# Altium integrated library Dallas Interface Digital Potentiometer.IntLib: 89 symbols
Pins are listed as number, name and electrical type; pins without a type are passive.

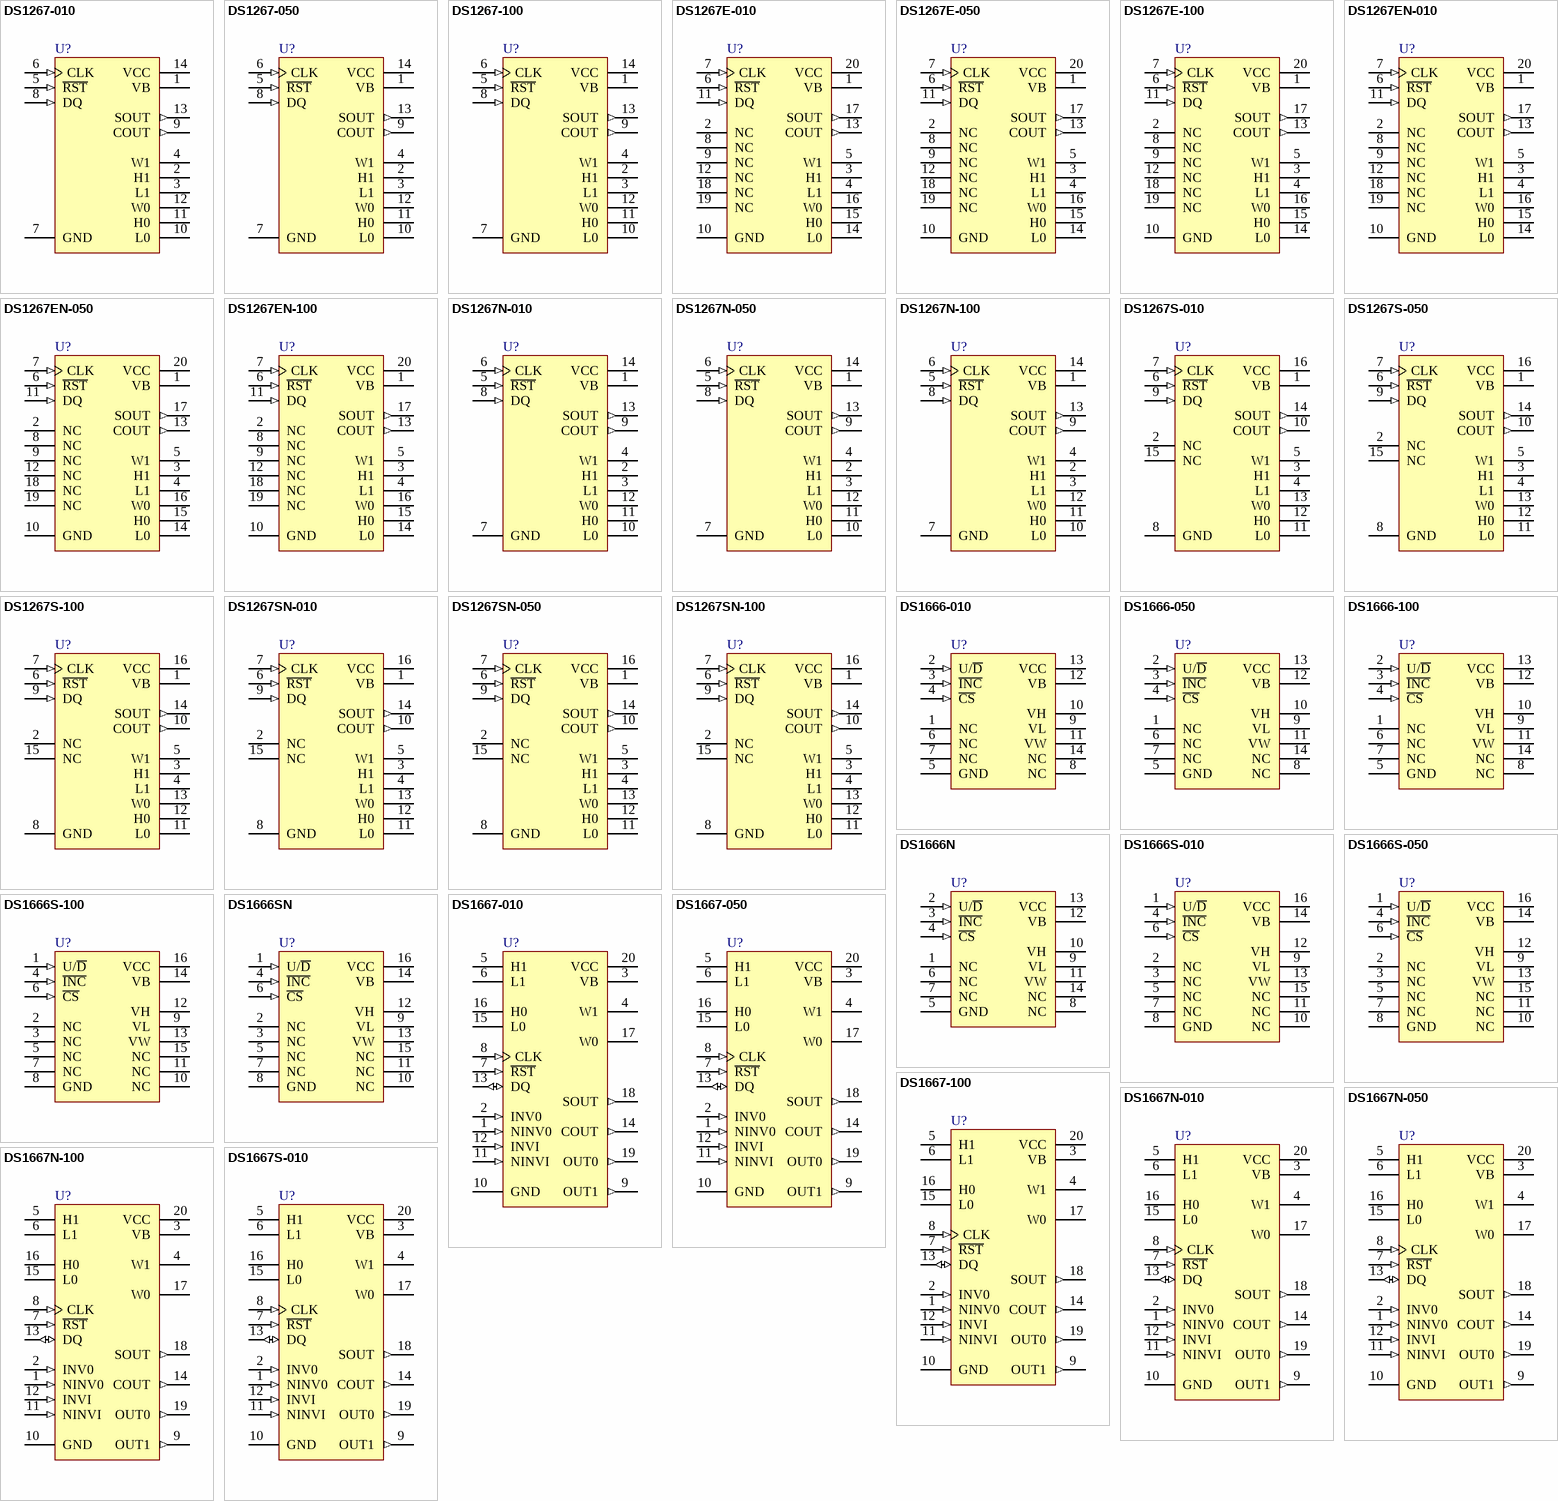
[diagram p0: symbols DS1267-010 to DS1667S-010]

## DS1267-010
designator U?
Dual Digital Potentiometer Chip
footprint DIP14 (DIP, 14-Leads, Row Spacing 7.62mm, Pitch 2.54mm, Body 19.31x6.35mm)
pins: 1 VB (power), 2 H1, 3 L1, 4 W1, 5 ~{RST} (in), 6 CLK (in), 7 GND (power), 8 DQ (in), 9 COUT (out), 10 L0, 11 H0, 12 W0, 13 SOUT (out), 14 VCC (power)

## DS1267-050
designator U?
Dual Digital Potentiometer Chip
footprint DIP14 (DIP, 14-Leads, Row Spacing 7.62mm, Pitch 2.54mm, Body 19.31x6.35mm)
pins: 1 VB (power), 2 H1, 3 L1, 4 W1, 5 ~{RST} (in), 6 CLK (in), 7 GND (power), 8 DQ (in), 9 COUT (out), 10 L0, 11 H0, 12 W0, 13 SOUT (out), 14 VCC (power)

## DS1267-100
designator U?
Dual Digital Potentiometer Chip
footprint DIP14 (DIP, 14-Leads, Row Spacing 7.62mm, Pitch 2.54mm, Body 19.31x6.35mm)
pins: 1 VB (power), 2 H1, 3 L1, 4 W1, 5 ~{RST} (in), 6 CLK (in), 7 GND (power), 8 DQ (in), 9 COUT (out), 10 L0, 11 H0, 12 W0, 13 SOUT (out), 14 VCC (power)

## DS1267E-010
designator U?
Dual Digital Potentiometer Chip; Note: Pin numbers 2, 8, 9, 12, 18 and 19 are Not Connected (NC)
footprint TSSOP20_N (TSOP, 20-Leads, Body 6.5x4.4mm, Pitch 0.65mm, IPC Medium Density)
footprint TSSOP20_L (TSOP, 20-Leads, Body 6.5x4.4mm, Pitch 0.65mm, IPC High Density)
footprint TSSOP20_M (TSOP, 20-Leads, Body 6.5x4.4mm, Pitch 0.65mm, IPC Low Density)
pins: 1 VB (power), 2 NC, 3 H1, 4 L1, 5 W1, 6 ~{RST} (in), 7 CLK (in), 8 NC, 9 NC, 10 GND (power), 11 DQ (in), 12 NC, 13 COUT (out), 14 L0, 15 H0, 16 W0, 17 SOUT (out), 18 NC, 19 NC, 20 VCC (power)

## DS1267E-050
designator U?
Dual Digital Potentiometer Chip; Note: Pin numbers 2, 8, 9, 12, 18 and 19 are Not Connected (NC)
footprint TSSOP20_N (TSOP, 20-Leads, Body 6.5x4.4mm, Pitch 0.65mm, IPC Medium Density)
footprint TSSOP20_L (TSOP, 20-Leads, Body 6.5x4.4mm, Pitch 0.65mm, IPC High Density)
footprint TSSOP20_M (TSOP, 20-Leads, Body 6.5x4.4mm, Pitch 0.65mm, IPC Low Density)
pins: 1 VB (power), 2 NC, 3 H1, 4 L1, 5 W1, 6 ~{RST} (in), 7 CLK (in), 8 NC, 9 NC, 10 GND (power), 11 DQ (in), 12 NC, 13 COUT (out), 14 L0, 15 H0, 16 W0, 17 SOUT (out), 18 NC, 19 NC, 20 VCC (power)

## DS1267E-100
designator U?
Dual Digital Potentiometer Chip; Note: Pin numbers 2, 8, 9, 12, 18 and 19 are Not Connected (NC)
footprint TSSOP20_N (TSOP, 20-Leads, Body 6.5x4.4mm, Pitch 0.65mm, IPC Medium Density)
footprint TSSOP20_L (TSOP, 20-Leads, Body 6.5x4.4mm, Pitch 0.65mm, IPC High Density)
footprint TSSOP20_M (TSOP, 20-Leads, Body 6.5x4.4mm, Pitch 0.65mm, IPC Low Density)
pins: 1 VB (power), 2 NC, 3 H1, 4 L1, 5 W1, 6 ~{RST} (in), 7 CLK (in), 8 NC, 9 NC, 10 GND (power), 11 DQ (in), 12 NC, 13 COUT (out), 14 L0, 15 H0, 16 W0, 17 SOUT (out), 18 NC, 19 NC, 20 VCC (power)

## DS1267EN-010
designator U?
Dual Digital Potentiometer Chip; Note: Pin numbers 2, 8, 9, 12, 18 and 19 are Not Connected (NC)
footprint TSSOP20_N (TSOP, 20-Leads, Body 6.5x4.4mm, Pitch 0.65mm, IPC Medium Density)
footprint TSSOP20_L (TSOP, 20-Leads, Body 6.5x4.4mm, Pitch 0.65mm, IPC High Density)
footprint TSSOP20_M (TSOP, 20-Leads, Body 6.5x4.4mm, Pitch 0.65mm, IPC Low Density)
pins: 1 VB (power), 2 NC, 3 H1, 4 L1, 5 W1, 6 ~{RST} (in), 7 CLK (in), 8 NC, 9 NC, 10 GND (power), 11 DQ (in), 12 NC, 13 COUT (out), 14 L0, 15 H0, 16 W0, 17 SOUT (out), 18 NC, 19 NC, 20 VCC (power)

## DS1267EN-050
designator U?
Dual Digital Potentiometer Chip; Note: Pin numbers 2, 8, 9, 12, 18 and 19 are Not Connected (NC)
footprint TSSOP20_N (TSOP, 20-Leads, Body 6.5x4.4mm, Pitch 0.65mm, IPC Medium Density)
footprint TSSOP20_L (TSOP, 20-Leads, Body 6.5x4.4mm, Pitch 0.65mm, IPC High Density)
footprint TSSOP20_M (TSOP, 20-Leads, Body 6.5x4.4mm, Pitch 0.65mm, IPC Low Density)
pins: 1 VB (power), 2 NC, 3 H1, 4 L1, 5 W1, 6 ~{RST} (in), 7 CLK (in), 8 NC, 9 NC, 10 GND (power), 11 DQ (in), 12 NC, 13 COUT (out), 14 L0, 15 H0, 16 W0, 17 SOUT (out), 18 NC, 19 NC, 20 VCC (power)

## DS1267EN-100
designator U?
Dual Digital Potentiometer Chip; Note: Pin numbers 2, 8, 9, 12, 18 and 19 are Not Connected (NC)
footprint TSSOP20_N (TSOP, 20-Leads, Body 6.5x4.4mm, Pitch 0.65mm, IPC Medium Density)
footprint TSSOP20_L (TSOP, 20-Leads, Body 6.5x4.4mm, Pitch 0.65mm, IPC High Density)
footprint TSSOP20_M (TSOP, 20-Leads, Body 6.5x4.4mm, Pitch 0.65mm, IPC Low Density)
pins: 1 VB (power), 2 NC, 3 H1, 4 L1, 5 W1, 6 ~{RST} (in), 7 CLK (in), 8 NC, 9 NC, 10 GND (power), 11 DQ (in), 12 NC, 13 COUT (out), 14 L0, 15 H0, 16 W0, 17 SOUT (out), 18 NC, 19 NC, 20 VCC (power)

## DS1267N-010
designator U?
Dual Digital Potentiometer Chip
footprint DIP14 (DIP, 14-Leads, Row Spacing 7.62mm, Pitch 2.54mm, Body 19.31x6.35mm)
pins: 1 VB (power), 2 H1, 3 L1, 4 W1, 5 ~{RST} (in), 6 CLK (in), 7 GND (power), 8 DQ (in), 9 COUT (out), 10 L0, 11 H0, 12 W0, 13 SOUT (out), 14 VCC (power)

## DS1267N-050
designator U?
Dual Digital Potentiometer Chip
footprint DIP14 (DIP, 14-Leads, Row Spacing 7.62mm, Pitch 2.54mm, Body 19.31x6.35mm)
pins: 1 VB (power), 2 H1, 3 L1, 4 W1, 5 ~{RST} (in), 6 CLK (in), 7 GND (power), 8 DQ (in), 9 COUT (out), 10 L0, 11 H0, 12 W0, 13 SOUT (out), 14 VCC (power)

## DS1267N-100
designator U?
Dual Digital Potentiometer Chip
footprint DIP14 (DIP, 14-Leads, Row Spacing 7.62mm, Pitch 2.54mm, Body 19.31x6.35mm)
pins: 1 VB (power), 2 H1, 3 L1, 4 W1, 5 ~{RST} (in), 6 CLK (in), 7 GND (power), 8 DQ (in), 9 COUT (out), 10 L0, 11 H0, 12 W0, 13 SOUT (out), 14 VCC (power)

## DS1267S-010
designator U?
Dual Digital Potentiometer Chip; Note: Pin numbers 2 and 15 are Not Connected (NC)
footprint SOIC16W_N (SOIC, 16-Leads, Body 10.3x7.5mm, Pitch 1.27mm, IPC Medium Density)
footprint SOIC16W_L (SOIC, 16-Leads, Body 10.3x7.5mm, Pitch 1.27mm, IPC High Density)
footprint SOIC16W_M (SOIC, 16-Leads, Body 10.3x7.5mm, Pitch 1.27mm, IPC Low Density)
pins: 1 VB (power), 2 NC, 3 H1, 4 L1, 5 W1, 6 ~{RST} (in), 7 CLK (in), 8 GND (power), 9 DQ (in), 10 COUT (out), 11 L0, 12 H0, 13 W0, 14 SOUT (out), 15 NC, 16 VCC (power)

## DS1267S-050
designator U?
Dual Digital Potentiometer Chip; Note: Pin numbers 2 and 15 are Not Connected (NC)
footprint SOIC16W_N (SOIC, 16-Leads, Body 10.3x7.5mm, Pitch 1.27mm, IPC Medium Density)
footprint SOIC16W_L (SOIC, 16-Leads, Body 10.3x7.5mm, Pitch 1.27mm, IPC High Density)
footprint SOIC16W_M (SOIC, 16-Leads, Body 10.3x7.5mm, Pitch 1.27mm, IPC Low Density)
pins: 1 VB (power), 2 NC, 3 H1, 4 L1, 5 W1, 6 ~{RST} (in), 7 CLK (in), 8 GND (power), 9 DQ (in), 10 COUT (out), 11 L0, 12 H0, 13 W0, 14 SOUT (out), 15 NC, 16 VCC (power)

## DS1267S-100
designator U?
Dual Digital Potentiometer Chip; Note: Pin numbers 2 and 15 are Not Connected (NC)
footprint SOIC16W_N (SOIC, 16-Leads, Body 10.3x7.5mm, Pitch 1.27mm, IPC Medium Density)
footprint SOIC16W_L (SOIC, 16-Leads, Body 10.3x7.5mm, Pitch 1.27mm, IPC High Density)
footprint SOIC16W_M (SOIC, 16-Leads, Body 10.3x7.5mm, Pitch 1.27mm, IPC Low Density)
pins: 1 VB (power), 2 NC, 3 H1, 4 L1, 5 W1, 6 ~{RST} (in), 7 CLK (in), 8 GND (power), 9 DQ (in), 10 COUT (out), 11 L0, 12 H0, 13 W0, 14 SOUT (out), 15 NC, 16 VCC (power)

## DS1267SN-010
designator U?
Dual Digital Potentiometer Chip; Note: Pin numbers 2 and 15 are Not Connected (NC)
footprint SOIC16W_N (SOIC, 16-Leads, Body 10.3x7.5mm, Pitch 1.27mm, IPC Medium Density)
footprint SOIC16W_L (SOIC, 16-Leads, Body 10.3x7.5mm, Pitch 1.27mm, IPC High Density)
footprint SOIC16W_M (SOIC, 16-Leads, Body 10.3x7.5mm, Pitch 1.27mm, IPC Low Density)
pins: 1 VB (power), 2 NC, 3 H1, 4 L1, 5 W1, 6 ~{RST} (in), 7 CLK (in), 8 GND (power), 9 DQ (in), 10 COUT (out), 11 L0, 12 H0, 13 W0, 14 SOUT (out), 15 NC, 16 VCC (power)

## DS1267SN-050
designator U?
Dual Digital Potentiometer Chip; Note: Pin numbers 2 and 15 are Not Connected (NC)
footprint SOIC16W_N (SOIC, 16-Leads, Body 10.3x7.5mm, Pitch 1.27mm, IPC Medium Density)
footprint SOIC16W_L (SOIC, 16-Leads, Body 10.3x7.5mm, Pitch 1.27mm, IPC High Density)
footprint SOIC16W_M (SOIC, 16-Leads, Body 10.3x7.5mm, Pitch 1.27mm, IPC Low Density)
pins: 1 VB (power), 2 NC, 3 H1, 4 L1, 5 W1, 6 ~{RST} (in), 7 CLK (in), 8 GND (power), 9 DQ (in), 10 COUT (out), 11 L0, 12 H0, 13 W0, 14 SOUT (out), 15 NC, 16 VCC (power)

## DS1267SN-100
designator U?
Dual Digital Potentiometer Chip; Note: Pin numbers 2 and 15 are Not Connected (NC)
footprint SOIC16W_N (SOIC, 16-Leads, Body 10.3x7.5mm, Pitch 1.27mm, IPC Medium Density)
footprint SOIC16W_L (SOIC, 16-Leads, Body 10.3x7.5mm, Pitch 1.27mm, IPC High Density)
footprint SOIC16W_M (SOIC, 16-Leads, Body 10.3x7.5mm, Pitch 1.27mm, IPC Low Density)
pins: 1 VB (power), 2 NC, 3 H1, 4 L1, 5 W1, 6 ~{RST} (in), 7 CLK (in), 8 GND (power), 9 DQ (in), 10 COUT (out), 11 L0, 12 H0, 13 W0, 14 SOUT (out), 15 NC, 16 VCC (power)

## DS1666-010
designator U?
Audio Digital Resistor; Note: Pin numbers 1, 6, 7, 8 and 14 are Not Connected (NC)
footprint DIP14 (DIP, 14-Leads, Row Spacing 7.62mm, Pitch 2.54mm, Body 19.31x6.35mm)
pins: 1 NC, 2 U/~{D} (in), 3 ~{INC} (in), 4 ~{CS} (in), 5 GND (power), 6 NC, 7 NC, 8 NC, 9 VL, 10 VH, 11 VW, 12 VB (power), 13 VCC (power), 14 NC

## DS1666-050
designator U?
Audio Digital Resistor; Note: Pin numbers 1, 6, 7, 8 and 14 are Not Connected (NC)
footprint DIP14 (DIP, 14-Leads, Row Spacing 7.62mm, Pitch 2.54mm, Body 19.31x6.35mm)
pins: 1 NC, 2 U/~{D} (in), 3 ~{INC} (in), 4 ~{CS} (in), 5 GND (power), 6 NC, 7 NC, 8 NC, 9 VL, 10 VH, 11 VW, 12 VB (power), 13 VCC (power), 14 NC

## DS1666-100
designator U?
Audio Digital Resistor; Note: Pin numbers 1, 6, 7, 8 and 14 are Not Connected (NC)
footprint DIP14 (DIP, 14-Leads, Row Spacing 7.62mm, Pitch 2.54mm, Body 19.31x6.35mm)
pins: 1 NC, 2 U/~{D} (in), 3 ~{INC} (in), 4 ~{CS} (in), 5 GND (power), 6 NC, 7 NC, 8 NC, 9 VL, 10 VH, 11 VW, 12 VB (power), 13 VCC (power), 14 NC

## DS1666N
designator U?
Audio Digital Resistor; Note: Pin numbers 1, 6, 7, 8 and 14 are Not Connected (NC)
footprint DIP14 (DIP, 14-Leads, Row Spacing 7.62mm, Pitch 2.54mm, Body 19.31x6.35mm)
pins: 1 NC, 2 U/~{D} (in), 3 ~{INC} (in), 4 ~{CS} (in), 5 GND (power), 6 NC, 7 NC, 8 NC, 9 VL, 10 VH, 11 VW, 12 VB (power), 13 VCC (power), 14 NC

## DS1666S-010
designator U?
Audio Digital Resistor; Note: Pin numbers 2, 3, 5, 7, 10, 11 and 15 are Not Connected (NC)
footprint SOIC16W_N (SOIC, 16-Leads, Body 10.3x7.5mm, Pitch 1.27mm, IPC Medium Density)
footprint SOIC16W_L (SOIC, 16-Leads, Body 10.3x7.5mm, Pitch 1.27mm, IPC High Density)
footprint SOIC16W_M (SOIC, 16-Leads, Body 10.3x7.5mm, Pitch 1.27mm, IPC Low Density)
pins: 1 U/~{D} (in), 2 NC, 3 NC, 4 ~{INC} (in), 5 NC, 6 ~{CS} (in), 7 NC, 8 GND (power), 9 VL, 10 NC, 11 NC, 12 VH, 13 VW, 14 VB (power), 15 NC, 16 VCC (power)

## DS1666S-050
designator U?
Audio Digital Resistor; Note: Pin numbers 2, 3, 5, 7, 10, 11 and 15 are Not Connected (NC)
footprint SOIC16W_N (SOIC, 16-Leads, Body 10.3x7.5mm, Pitch 1.27mm, IPC Medium Density)
footprint SOIC16W_L (SOIC, 16-Leads, Body 10.3x7.5mm, Pitch 1.27mm, IPC High Density)
footprint SOIC16W_M (SOIC, 16-Leads, Body 10.3x7.5mm, Pitch 1.27mm, IPC Low Density)
pins: 1 U/~{D} (in), 2 NC, 3 NC, 4 ~{INC} (in), 5 NC, 6 ~{CS} (in), 7 NC, 8 GND (power), 9 VL, 10 NC, 11 NC, 12 VH, 13 VW, 14 VB (power), 15 NC, 16 VCC (power)

## DS1666S-100
designator U?
Audio Digital Resistor; Note: Pin numbers 2, 3, 5, 7, 10, 11 and 15 are Not Connected (NC)
footprint SOIC16W_N (SOIC, 16-Leads, Body 10.3x7.5mm, Pitch 1.27mm, IPC Medium Density)
footprint SOIC16W_L (SOIC, 16-Leads, Body 10.3x7.5mm, Pitch 1.27mm, IPC High Density)
footprint SOIC16W_M (SOIC, 16-Leads, Body 10.3x7.5mm, Pitch 1.27mm, IPC Low Density)
pins: 1 U/~{D} (in), 2 NC, 3 NC, 4 ~{INC} (in), 5 NC, 6 ~{CS} (in), 7 NC, 8 GND (power), 9 VL, 10 NC, 11 NC, 12 VH, 13 VW, 14 VB (power), 15 NC, 16 VCC (power)

## DS1666SN
designator U?
Audio Digital Resistor; Note: Pin numbers 2, 3, 5, 7, 10, 11 and 15 are Not Connected (NC)
footprint SOIC16W_N (SOIC, 16-Leads, Body 10.3x7.5mm, Pitch 1.27mm, IPC Medium Density)
footprint SOIC16W_L (SOIC, 16-Leads, Body 10.3x7.5mm, Pitch 1.27mm, IPC High Density)
footprint SOIC16W_M (SOIC, 16-Leads, Body 10.3x7.5mm, Pitch 1.27mm, IPC Low Density)
pins: 1 U/~{D} (in), 2 NC, 3 NC, 4 ~{INC} (in), 5 NC, 6 ~{CS} (in), 7 NC, 8 GND (power), 9 VL, 10 NC, 11 NC, 12 VH, 13 VW, 14 VB (power), 15 NC, 16 VCC (power)

## DS1667-010
designator U?
Digital Resistor with Op Amp
footprint DIP20 (DIP, 20-Leads, Row Spacing 7.62mm, Pitch 2.54mm, Body 25.53x6.48mm)
pins: 1 NINV0 (in), 2 INV0 (in), 3 VB (power), 4 W1, 5 H1, 6 L1, 7 ~{RST} (in), 8 CLK (in), 9 OUT1 (out), 10 GND (power), 11 NINVI (in), 12 INVI (in), 13 DQ (io), 14 COUT (out), 15 L0, 16 H0, 17 W0, 18 SOUT (out), 19 OUT0 (out), 20 VCC (power)

## DS1667-050
designator U?
Digital Resistor with Op Amp
footprint DIP20 (DIP, 20-Leads, Row Spacing 7.62mm, Pitch 2.54mm, Body 25.53x6.48mm)
pins: 1 NINV0 (in), 2 INV0 (in), 3 VB (power), 4 W1, 5 H1, 6 L1, 7 ~{RST} (in), 8 CLK (in), 9 OUT1 (out), 10 GND (power), 11 NINVI (in), 12 INVI (in), 13 DQ (io), 14 COUT (out), 15 L0, 16 H0, 17 W0, 18 SOUT (out), 19 OUT0 (out), 20 VCC (power)

## DS1667-100
designator U?
Digital Resistor with Op Amp
footprint DIP20 (DIP, 20-Leads, Row Spacing 7.62mm, Pitch 2.54mm, Body 25.53x6.48mm)
pins: 1 NINV0 (in), 2 INV0 (in), 3 VB (power), 4 W1, 5 H1, 6 L1, 7 ~{RST} (in), 8 CLK (in), 9 OUT1 (out), 10 GND (power), 11 NINVI (in), 12 INVI (in), 13 DQ (io), 14 COUT (out), 15 L0, 16 H0, 17 W0, 18 SOUT (out), 19 OUT0 (out), 20 VCC (power)

## DS1667N-010
designator U?
Digital Resistor with Op Amp
footprint DIP20 (DIP, 20-Leads, Row Spacing 7.62mm, Pitch 2.54mm, Body 25.53x6.48mm)
pins: 1 NINV0 (in), 2 INV0 (in), 3 VB (power), 4 W1, 5 H1, 6 L1, 7 ~{RST} (in), 8 CLK (in), 9 OUT1 (out), 10 GND (power), 11 NINVI (in), 12 INVI (in), 13 DQ (io), 14 COUT (out), 15 L0, 16 H0, 17 W0, 18 SOUT (out), 19 OUT0 (out), 20 VCC (power)

## DS1667N-050
designator U?
Digital Resistor with Op Amp
footprint DIP20 (DIP, 20-Leads, Row Spacing 7.62mm, Pitch 2.54mm, Body 25.53x6.48mm)
pins: 1 NINV0 (in), 2 INV0 (in), 3 VB (power), 4 W1, 5 H1, 6 L1, 7 ~{RST} (in), 8 CLK (in), 9 OUT1 (out), 10 GND (power), 11 NINVI (in), 12 INVI (in), 13 DQ (io), 14 COUT (out), 15 L0, 16 H0, 17 W0, 18 SOUT (out), 19 OUT0 (out), 20 VCC (power)

## DS1667N-100
designator U?
Digital Resistor with Op Amp
footprint DIP20 (DIP, 20-Leads, Row Spacing 7.62mm, Pitch 2.54mm, Body 25.53x6.48mm)
pins: 1 NINV0 (in), 2 INV0 (in), 3 VB (power), 4 W1, 5 H1, 6 L1, 7 ~{RST} (in), 8 CLK (in), 9 OUT1 (out), 10 GND (power), 11 NINVI (in), 12 INVI (in), 13 DQ (io), 14 COUT (out), 15 L0, 16 H0, 17 W0, 18 SOUT (out), 19 OUT0 (out), 20 VCC (power)

## DS1667S-010
designator U?
Digital Resistor with Op Amp
footprint SOIC20_N (SOIC, 20-Leads, Body 12.8x7.5mm, Pitch 1.27mm, IPC Medium Density)
footprint SOIC20_L (SOIC, 20-Leads, Body 12.8x7.5mm, Pitch 1.27mm, IPC High Density)
footprint SOIC20_M (SOIC, 20-Leads, Body 12.8x7.5mm, Pitch 1.27mm, IPC Low Density)
pins: 1 NINV0 (in), 2 INV0 (in), 3 VB (power), 4 W1, 5 H1, 6 L1, 7 ~{RST} (in), 8 CLK (in), 9 OUT1 (out), 10 GND (power), 11 NINVI (in), 12 INVI (in), 13 DQ (io), 14 COUT (out), 15 L0, 16 H0, 17 W0, 18 SOUT (out), 19 OUT0 (out), 20 VCC (power)

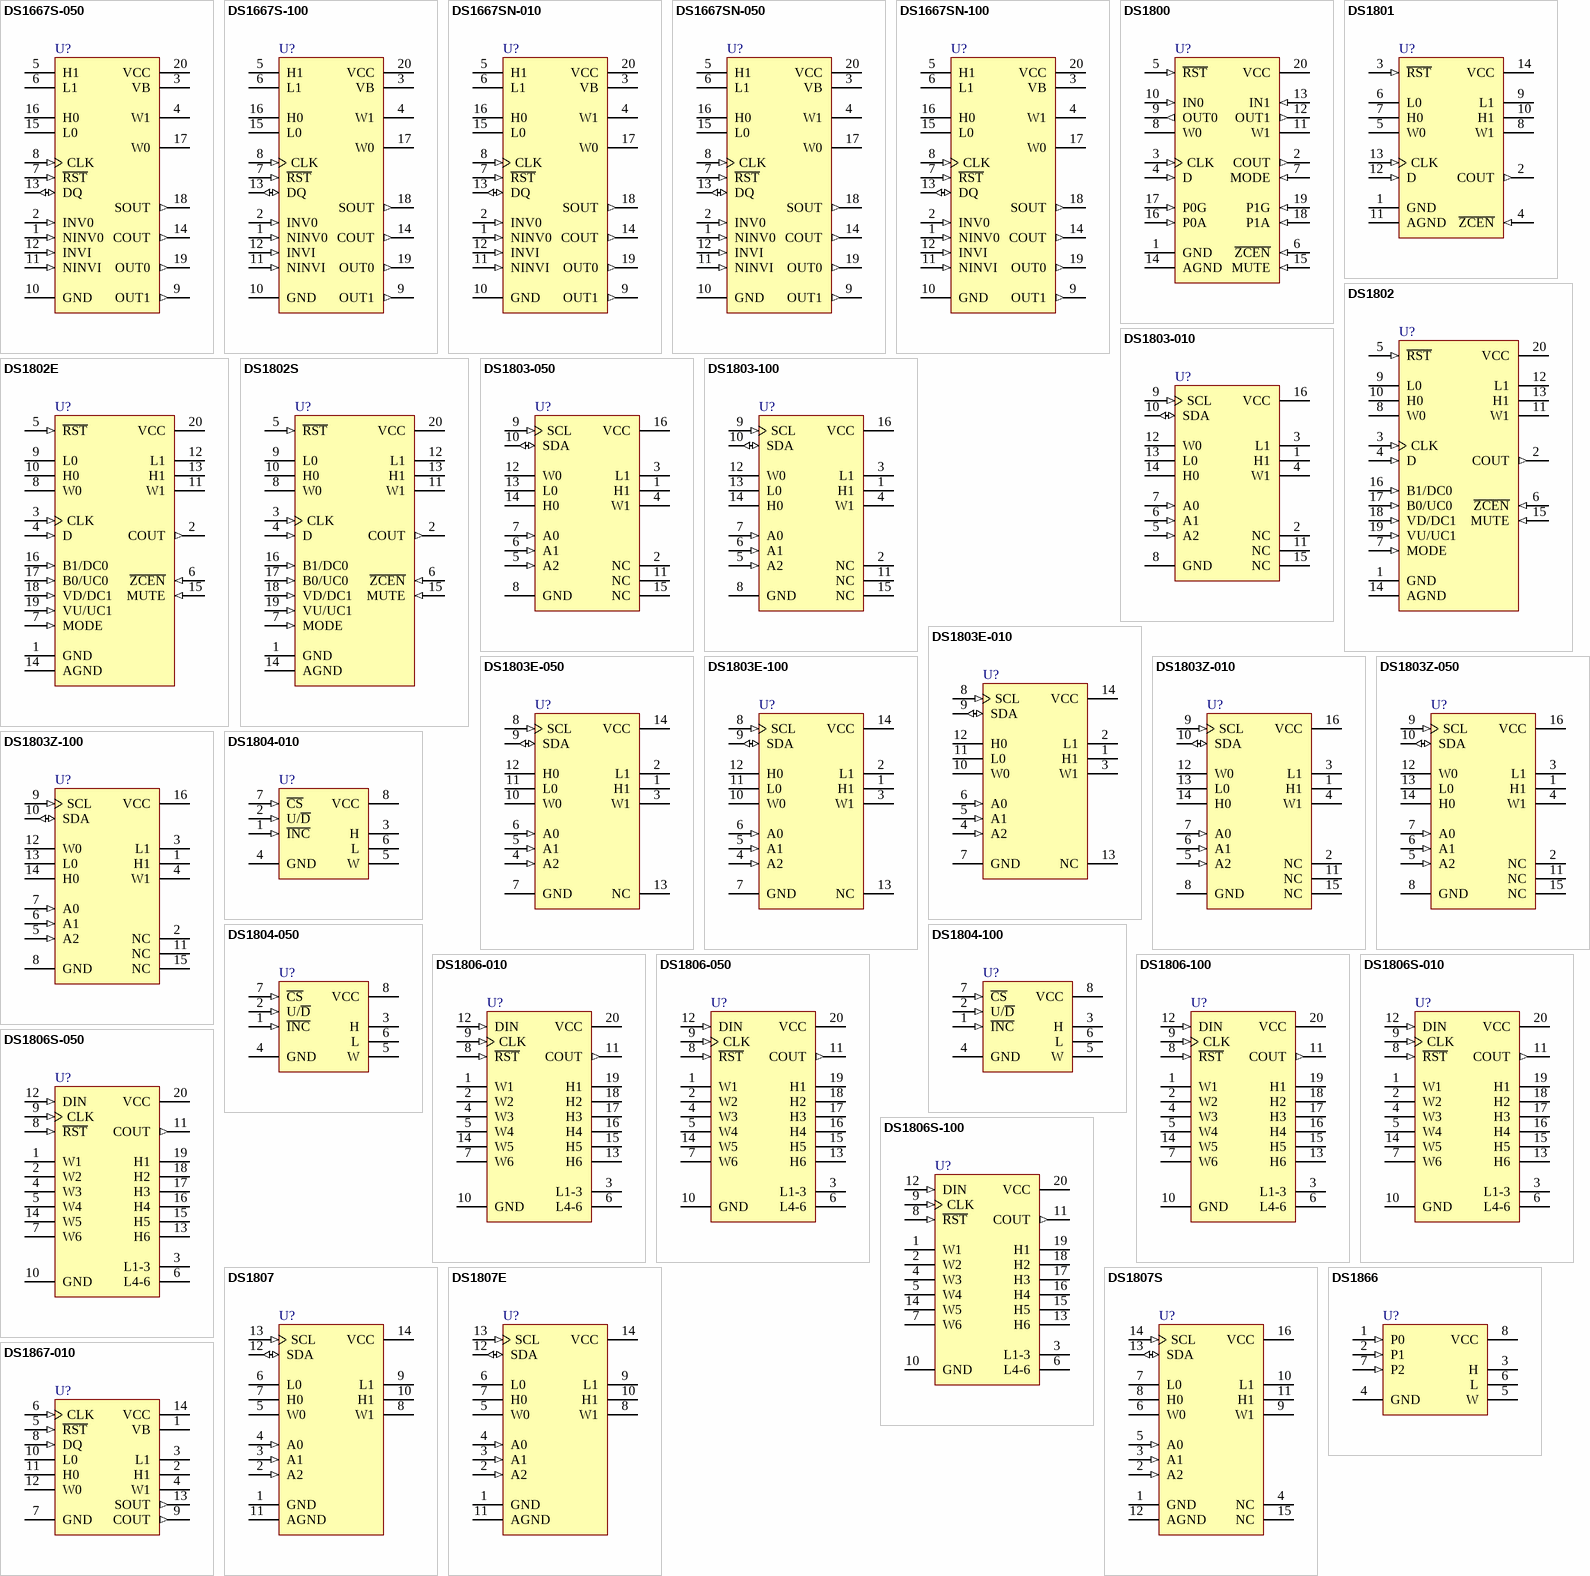
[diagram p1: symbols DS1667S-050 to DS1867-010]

## DS1667S-050
designator U?
Digital Resistor with Op Amp
footprint SOIC20_N (SOIC, 20-Leads, Body 12.8x7.5mm, Pitch 1.27mm, IPC Medium Density)
footprint SOIC20_L (SOIC, 20-Leads, Body 12.8x7.5mm, Pitch 1.27mm, IPC High Density)
footprint SOIC20_M (SOIC, 20-Leads, Body 12.8x7.5mm, Pitch 1.27mm, IPC Low Density)
pins: 1 NINV0 (in), 2 INV0 (in), 3 VB (power), 4 W1, 5 H1, 6 L1, 7 ~{RST} (in), 8 CLK (in), 9 OUT1 (out), 10 GND (power), 11 NINVI (in), 12 INVI (in), 13 DQ (io), 14 COUT (out), 15 L0, 16 H0, 17 W0, 18 SOUT (out), 19 OUT0 (out), 20 VCC (power)

## DS1667S-100
designator U?
Digital Resistor with Op Amp
footprint SOIC20_N (SOIC, 20-Leads, Body 12.8x7.5mm, Pitch 1.27mm, IPC Medium Density)
footprint SOIC20_L (SOIC, 20-Leads, Body 12.8x7.5mm, Pitch 1.27mm, IPC High Density)
footprint SOIC20_M (SOIC, 20-Leads, Body 12.8x7.5mm, Pitch 1.27mm, IPC Low Density)
pins: 1 NINV0 (in), 2 INV0 (in), 3 VB (power), 4 W1, 5 H1, 6 L1, 7 ~{RST} (in), 8 CLK (in), 9 OUT1 (out), 10 GND (power), 11 NINVI (in), 12 INVI (in), 13 DQ (io), 14 COUT (out), 15 L0, 16 H0, 17 W0, 18 SOUT (out), 19 OUT0 (out), 20 VCC (power)

## DS1667SN-010
designator U?
Digital Resistor with Op Amp
footprint SOIC20_N (SOIC, 20-Leads, Body 12.8x7.5mm, Pitch 1.27mm, IPC Medium Density)
footprint SOIC20_L (SOIC, 20-Leads, Body 12.8x7.5mm, Pitch 1.27mm, IPC High Density)
footprint SOIC20_M (SOIC, 20-Leads, Body 12.8x7.5mm, Pitch 1.27mm, IPC Low Density)
pins: 1 NINV0 (in), 2 INV0 (in), 3 VB (power), 4 W1, 5 H1, 6 L1, 7 ~{RST} (in), 8 CLK (in), 9 OUT1 (out), 10 GND (power), 11 NINVI (in), 12 INVI (in), 13 DQ (io), 14 COUT (out), 15 L0, 16 H0, 17 W0, 18 SOUT (out), 19 OUT0 (out), 20 VCC (power)

## DS1667SN-050
designator U?
Digital Resistor with Op Amp
footprint SOIC20_N (SOIC, 20-Leads, Body 12.8x7.5mm, Pitch 1.27mm, IPC Medium Density)
footprint SOIC20_L (SOIC, 20-Leads, Body 12.8x7.5mm, Pitch 1.27mm, IPC High Density)
footprint SOIC20_M (SOIC, 20-Leads, Body 12.8x7.5mm, Pitch 1.27mm, IPC Low Density)
pins: 1 NINV0 (in), 2 INV0 (in), 3 VB (power), 4 W1, 5 H1, 6 L1, 7 ~{RST} (in), 8 CLK (in), 9 OUT1 (out), 10 GND (power), 11 NINVI (in), 12 INVI (in), 13 DQ (io), 14 COUT (out), 15 L0, 16 H0, 17 W0, 18 SOUT (out), 19 OUT0 (out), 20 VCC (power)

## DS1667SN-100
designator U?
Digital Resistor with Op Amp
footprint SOIC20_N (SOIC, 20-Leads, Body 12.8x7.5mm, Pitch 1.27mm, IPC Medium Density)
footprint SOIC20_L (SOIC, 20-Leads, Body 12.8x7.5mm, Pitch 1.27mm, IPC High Density)
footprint SOIC20_M (SOIC, 20-Leads, Body 12.8x7.5mm, Pitch 1.27mm, IPC Low Density)
pins: 1 NINV0 (in), 2 INV0 (in), 3 VB (power), 4 W1, 5 H1, 6 L1, 7 ~{RST} (in), 8 CLK (in), 9 OUT1 (out), 10 GND (power), 11 NINVI (in), 12 INVI (in), 13 DQ (io), 14 COUT (out), 15 L0, 16 H0, 17 W0, 18 SOUT (out), 19 OUT0 (out), 20 VCC (power)

## DS1800
designator U?
Dual Inverting Log Gain/Attenuator
footprint DIP20 (DIP, 20-Leads, Row Spacing 7.62mm, Pitch 2.54mm, Body 25.53x6.48mm)
pins: 1 GND (power), 2 COUT (out), 3 CLK (in), 4 D (in), 5 ~{RST} (in), 6 ~{ZCEN} (in), 7 MODE (in), 8 W0, 9 OUT0 (out), 10 IN0 (in), 11 W1, 12 OUT1 (out), 13 IN1 (in), 14 AGND (power), 15 MUTE (in), 16 P0A (in), 17 P0G (in), 18 P1A (in), 19 P1G (in), 20 VCC (power)

## DS1801
designator U?
Dual Audio Taper Potentiometer
footprint DIP14 (DIP, 14-Leads, Row Spacing 7.62mm, Pitch 2.54mm, Body 19.31x6.35mm)
pins: 1 GND (power), 2 COUT (out), 3 ~{RST} (in), 4 ~{ZCEN} (in), 5 W0, 6 L0, 7 H0, 8 W1, 9 L1, 10 H1, 11 AGND (power), 12 D (in), 13 CLK (in), 14 VCC (power)

## DS1802
designator U?
Dual Audio Taper Potentiometer with Pushbutton Control
footprint DIP20 (DIP, 20-Leads, Row Spacing 7.62mm, Pitch 2.54mm, Body 25.53x6.48mm)
pins: 1 GND (power), 2 COUT (out), 3 CLK (in), 4 D (in), 5 ~{RST} (in), 6 ~{ZCEN} (in), 7 MODE (in), 8 W0, 9 L0, 10 H0, 11 W1, 12 L1, 13 H1, 14 AGND (power), 15 MUTE (in), 16 B1/DC0 (in), 17 B0/UC0 (in), 18 VD/DC1 (in), 19 VU/UC1 (in), 20 VCC (power)

## DS1802E
designator U?
Dual Audio Taper Potentiometer with Pushbutton Control
footprint TSSOP20_N (TSOP, 20-Leads, Body 6.5x4.4mm, Pitch 0.65mm, IPC Medium Density)
footprint TSSOP20_L (TSOP, 20-Leads, Body 6.5x4.4mm, Pitch 0.65mm, IPC High Density)
footprint TSSOP20_M (TSOP, 20-Leads, Body 6.5x4.4mm, Pitch 0.65mm, IPC Low Density)
pins: 1 GND (power), 2 COUT (out), 3 CLK (in), 4 D (in), 5 ~{RST} (in), 6 ~{ZCEN} (in), 7 MODE (in), 8 W0, 9 L0, 10 H0, 11 W1, 12 L1, 13 H1, 14 AGND (power), 15 MUTE (in), 16 B1/DC0 (in), 17 B0/UC0 (in), 18 VD/DC1 (in), 19 VU/UC1 (in), 20 VCC (power)

## DS1802S
designator U?
Dual Audio Taper Potentiometer with Pushbutton Control
footprint SOIC20_N (SOIC, 20-Leads, Body 12.8x7.5mm, Pitch 1.27mm, IPC Medium Density)
footprint SOIC20_L (SOIC, 20-Leads, Body 12.8x7.5mm, Pitch 1.27mm, IPC High Density)
footprint SOIC20_M (SOIC, 20-Leads, Body 12.8x7.5mm, Pitch 1.27mm, IPC Low Density)
pins: 1 GND (power), 2 COUT (out), 3 CLK (in), 4 D (in), 5 ~{RST} (in), 6 ~{ZCEN} (in), 7 MODE (in), 8 W0, 9 L0, 10 H0, 11 W1, 12 L1, 13 H1, 14 AGND (power), 15 MUTE (in), 16 B1/DC0 (in), 17 B0/UC0 (in), 18 VD/DC1 (in), 19 VU/UC1 (in), 20 VCC (power)

## DS1803-010
designator U?
Addressable Dual Digital Potentiometer
footprint DIP16 (DIP, 16-Leads, Row Spacing 7.62mm, Pitch 2.54mm, Body 19.31x6.35mm)
pins: 1 H1, 2 NC, 3 L1, 4 W1, 5 A2 (in), 6 A1 (in), 7 A0 (in), 8 GND (power), 9 SCL (in), 10 SDA (io), 11 NC, 12 W0, 13 L0, 14 H0, 15 NC, 16 VCC (power)

## DS1803-050
designator U?
Addressable Dual Digital Potentiometer
footprint DIP16 (DIP, 16-Leads, Row Spacing 7.62mm, Pitch 2.54mm, Body 19.31x6.35mm)
pins: 1 H1, 2 NC, 3 L1, 4 W1, 5 A2 (in), 6 A1 (in), 7 A0 (in), 8 GND (power), 9 SCL (in), 10 SDA (io), 11 NC, 12 W0, 13 L0, 14 H0, 15 NC, 16 VCC (power)

## DS1803-100
designator U?
Addressable Dual Digital Potentiometer
footprint DIP16 (DIP, 16-Leads, Row Spacing 7.62mm, Pitch 2.54mm, Body 19.31x6.35mm)
pins: 1 H1, 2 NC, 3 L1, 4 W1, 5 A2 (in), 6 A1 (in), 7 A0 (in), 8 GND (power), 9 SCL (in), 10 SDA (io), 11 NC, 12 W0, 13 L0, 14 H0, 15 NC, 16 VCC (power)

## DS1803E-010
designator U?
Addressable Dual Digital Potentiometer
footprint TSSOP14_N (TSOP, 14-Leads, Body 5x4.4mm, Pitch 0.65mm, IPC Medium Density)
footprint TSSOP14_L (TSOP, 14-Leads, Body 5x4.4mm, Pitch 0.65mm, IPC High Density)
footprint TSSOP14_M (TSOP, 14-Leads, Body 5x4.4mm, Pitch 0.65mm, IPC Low Density)
pins: 1 H1, 2 L1, 3 W1, 4 A2 (in), 5 A1 (in), 6 A0 (in), 7 GND (power), 8 SCL (in), 9 SDA (io), 10 W0, 11 L0, 12 H0, 13 NC, 14 VCC (power)

## DS1803E-050
designator U?
Addressable Dual Digital Potentiometer
footprint TSSOP14_N (TSOP, 14-Leads, Body 5x4.4mm, Pitch 0.65mm, IPC Medium Density)
footprint TSSOP14_L (TSOP, 14-Leads, Body 5x4.4mm, Pitch 0.65mm, IPC High Density)
footprint TSSOP14_M (TSOP, 14-Leads, Body 5x4.4mm, Pitch 0.65mm, IPC Low Density)
pins: 1 H1, 2 L1, 3 W1, 4 A2 (in), 5 A1 (in), 6 A0 (in), 7 GND (power), 8 SCL (in), 9 SDA (io), 10 W0, 11 L0, 12 H0, 13 NC, 14 VCC (power)

## DS1803E-100
designator U?
Addressable Dual Digital Potentiometer
footprint TSSOP14_N (TSOP, 14-Leads, Body 5x4.4mm, Pitch 0.65mm, IPC Medium Density)
footprint TSSOP14_L (TSOP, 14-Leads, Body 5x4.4mm, Pitch 0.65mm, IPC High Density)
footprint TSSOP14_M (TSOP, 14-Leads, Body 5x4.4mm, Pitch 0.65mm, IPC Low Density)
pins: 1 H1, 2 L1, 3 W1, 4 A2 (in), 5 A1 (in), 6 A0 (in), 7 GND (power), 8 SCL (in), 9 SDA (io), 10 W0, 11 L0, 12 H0, 13 NC, 14 VCC (power)

## DS1803Z-010
designator U?
Addressable Dual Digital Potentiometer
footprint SOIC16N_N (SOIC, 16-Leads, Body 9.9x3.9mm, Pitch 1.27mm, IPC Medium Density)
footprint SOIC16N_L (SOIC, 16-Leads, Body 9.9x3.9mm, Pitch 1.27mm, IPC High Density)
footprint SOIC16N_M (SOIC, 16-Leads, Body 9.9x3.9mm, Pitch 1.27mm, IPC Low Density)
pins: 1 H1, 2 NC, 3 L1, 4 W1, 5 A2 (in), 6 A1 (in), 7 A0 (in), 8 GND (power), 9 SCL (in), 10 SDA (io), 11 NC, 12 W0, 13 L0, 14 H0, 15 NC, 16 VCC (power)

## DS1803Z-050
designator U?
Addressable Dual Digital Potentiometer
footprint SOIC16N_N (SOIC, 16-Leads, Body 9.9x3.9mm, Pitch 1.27mm, IPC Medium Density)
footprint SOIC16N_L (SOIC, 16-Leads, Body 9.9x3.9mm, Pitch 1.27mm, IPC High Density)
footprint SOIC16N_M (SOIC, 16-Leads, Body 9.9x3.9mm, Pitch 1.27mm, IPC Low Density)
pins: 1 H1, 2 NC, 3 L1, 4 W1, 5 A2 (in), 6 A1 (in), 7 A0 (in), 8 GND (power), 9 SCL (in), 10 SDA (io), 11 NC, 12 W0, 13 L0, 14 H0, 15 NC, 16 VCC (power)

## DS1803Z-100
designator U?
Addressable Dual Digital Potentiometer
footprint SOIC16N_N (SOIC, 16-Leads, Body 9.9x3.9mm, Pitch 1.27mm, IPC Medium Density)
footprint SOIC16N_L (SOIC, 16-Leads, Body 9.9x3.9mm, Pitch 1.27mm, IPC High Density)
footprint SOIC16N_M (SOIC, 16-Leads, Body 9.9x3.9mm, Pitch 1.27mm, IPC Low Density)
pins: 1 H1, 2 NC, 3 L1, 4 W1, 5 A2 (in), 6 A1 (in), 7 A0 (in), 8 GND (power), 9 SCL (in), 10 SDA (io), 11 NC, 12 W0, 13 L0, 14 H0, 15 NC, 16 VCC (power)

## DS1804-010
designator U?
Nonvolatile Trimmer Potentiometer
footprint DIP8 (DIP, 8-Leads, Row Spacing 7.62mm, Pitch 2.54mm, Body 9.65x6.35mm)
pins: 1 ~{INC} (in), 2 U/~{D} (in), 3 H, 4 GND (power), 5 W, 6 L, 7 ~{CS} (in), 8 VCC (power)

## DS1804-050
designator U?
Nonvolatile Trimmer Potentiometer
footprint DIP8 (DIP, 8-Leads, Row Spacing 7.62mm, Pitch 2.54mm, Body 9.65x6.35mm)
pins: 1 ~{INC} (in), 2 U/~{D} (in), 3 H, 4 GND (power), 5 W, 6 L, 7 ~{CS} (in), 8 VCC (power)

## DS1804-100
designator U?
Nonvolatile Trimmer Potentiometer
footprint DIP8 (DIP, 8-Leads, Row Spacing 7.62mm, Pitch 2.54mm, Body 9.65x6.35mm)
pins: 1 ~{INC} (in), 2 U/~{D} (in), 3 H, 4 GND (power), 5 W, 6 L, 7 ~{CS} (in), 8 VCC (power)

## DS1806-010
designator U?
Digital Sextet Potentiometer
footprint DIP20 (DIP, 20-Leads, Row Spacing 7.62mm, Pitch 2.54mm, Body 25.53x6.48mm)
pins: 1 W1, 2 W2, 3 L1-3, 4 W3, 5 W4, 6 L4-6, 7 W6, 8 ~{RST} (in), 9 CLK (in), 10 GND (power), 11 COUT (out), 12 DIN (in), 13 H6, 14 W5, 15 H5, 16 H4, 17 H3, 18 H2, 19 H1, 20 VCC (power)

## DS1806-050
designator U?
Digital Sextet Potentiometer
footprint DIP20 (DIP, 20-Leads, Row Spacing 7.62mm, Pitch 2.54mm, Body 25.53x6.48mm)
pins: 1 W1, 2 W2, 3 L1-3, 4 W3, 5 W4, 6 L4-6, 7 W6, 8 ~{RST} (in), 9 CLK (in), 10 GND (power), 11 COUT (out), 12 DIN (in), 13 H6, 14 W5, 15 H5, 16 H4, 17 H3, 18 H2, 19 H1, 20 VCC (power)

## DS1806-100
designator U?
Digital Sextet Potentiometer
footprint DIP20 (DIP, 20-Leads, Row Spacing 7.62mm, Pitch 2.54mm, Body 25.53x6.48mm)
pins: 1 W1, 2 W2, 3 L1-3, 4 W3, 5 W4, 6 L4-6, 7 W6, 8 ~{RST} (in), 9 CLK (in), 10 GND (power), 11 COUT (out), 12 DIN (in), 13 H6, 14 W5, 15 H5, 16 H4, 17 H3, 18 H2, 19 H1, 20 VCC (power)

## DS1806S-010
designator U?
Digital Sextet Potentiometer
footprint SOIC20_N (SOIC, 20-Leads, Body 12.8x7.5mm, Pitch 1.27mm, IPC Medium Density)
footprint SOIC20_L (SOIC, 20-Leads, Body 12.8x7.5mm, Pitch 1.27mm, IPC High Density)
footprint SOIC20_M (SOIC, 20-Leads, Body 12.8x7.5mm, Pitch 1.27mm, IPC Low Density)
pins: 1 W1, 2 W2, 3 L1-3, 4 W3, 5 W4, 6 L4-6, 7 W6, 8 ~{RST} (in), 9 CLK (in), 10 GND (power), 11 COUT (out), 12 DIN (in), 13 H6, 14 W5, 15 H5, 16 H4, 17 H3, 18 H2, 19 H1, 20 VCC (power)

## DS1806S-050
designator U?
Digital Sextet Potentiometer
footprint SOIC20_N (SOIC, 20-Leads, Body 12.8x7.5mm, Pitch 1.27mm, IPC Medium Density)
footprint SOIC20_L (SOIC, 20-Leads, Body 12.8x7.5mm, Pitch 1.27mm, IPC High Density)
footprint SOIC20_M (SOIC, 20-Leads, Body 12.8x7.5mm, Pitch 1.27mm, IPC Low Density)
pins: 1 W1, 2 W2, 3 L1-3, 4 W3, 5 W4, 6 L4-6, 7 W6, 8 ~{RST} (in), 9 CLK (in), 10 GND (power), 11 COUT (out), 12 DIN (in), 13 H6, 14 W5, 15 H5, 16 H4, 17 H3, 18 H2, 19 H1, 20 VCC (power)

## DS1806S-100
designator U?
Digital Sextet Potentiometer
footprint SOIC20_N (SOIC, 20-Leads, Body 12.8x7.5mm, Pitch 1.27mm, IPC Medium Density)
footprint SOIC20_L (SOIC, 20-Leads, Body 12.8x7.5mm, Pitch 1.27mm, IPC High Density)
footprint SOIC20_M (SOIC, 20-Leads, Body 12.8x7.5mm, Pitch 1.27mm, IPC Low Density)
pins: 1 W1, 2 W2, 3 L1-3, 4 W3, 5 W4, 6 L4-6, 7 W6, 8 ~{RST} (in), 9 CLK (in), 10 GND (power), 11 COUT (out), 12 DIN (in), 13 H6, 14 W5, 15 H5, 16 H4, 17 H3, 18 H2, 19 H1, 20 VCC (power)

## DS1807
designator U?
Addressable Dual Audio Taper Potentiometer
footprint DIP14 (DIP, 14-Leads, Row Spacing 7.62mm, Pitch 2.54mm, Body 19.31x6.35mm)
pins: 1 GND (power), 2 A2 (in), 3 A1 (in), 4 A0 (in), 5 W0, 6 L0, 7 H0, 8 W1, 9 L1, 10 H1, 11 AGND (power), 12 SDA (io), 13 SCL (in), 14 VCC (power)

## DS1807E
designator U?
Addressable Dual Audio Taper Potentiometer
footprint TSSOP14_N (TSOP, 14-Leads, Body 5x4.4mm, Pitch 0.65mm, IPC Medium Density)
footprint TSSOP14_L (TSOP, 14-Leads, Body 5x4.4mm, Pitch 0.65mm, IPC High Density)
footprint TSSOP14_M (TSOP, 14-Leads, Body 5x4.4mm, Pitch 0.65mm, IPC Low Density)
pins: 1 GND (power), 2 A2 (in), 3 A1 (in), 4 A0 (in), 5 W0, 6 L0, 7 H0, 8 W1, 9 L1, 10 H1, 11 AGND (power), 12 SDA (io), 13 SCL (in), 14 VCC (power)

## DS1807S
designator U?
Addressable Dual Audio Taper Potentiometer; Note: Pin numbers 4 and 15 are Not Connected (NC)
footprint SOIC16W_N (SOIC, 16-Leads, Body 10.3x7.5mm, Pitch 1.27mm, IPC Medium Density)
footprint SOIC16W_L (SOIC, 16-Leads, Body 10.3x7.5mm, Pitch 1.27mm, IPC High Density)
footprint SOIC16W_M (SOIC, 16-Leads, Body 10.3x7.5mm, Pitch 1.27mm, IPC Low Density)
pins: 1 GND (power), 2 A2 (in), 3 A1 (in), 4 NC, 5 A0 (in), 6 W0, 7 L0, 8 H0, 9 W1, 10 L1, 11 H1, 12 AGND (power), 13 SDA (io), 14 SCL (in), 15 NC, 16 VCC (power)

## DS1866
designator U?
Log Trimmer Potentiometer
footprint DIP8 (DIP, 8-Leads, Row Spacing 7.62mm, Pitch 2.54mm, Body 9.65x6.35mm)
pins: 1 P0 (in), 2 P1 (in), 3 H, 4 GND (power), 5 W, 6 L, 7 P2 (in), 8 VCC (power)

## DS1867-010
designator U?
Dual Digital Potentiometer with EEPROM
footprint DIP14 (DIP, 14-Leads, Row Spacing 7.62mm, Pitch 2.54mm, Body 19.31x6.35mm)
pins: 1 VB (power), 2 H1, 3 L1, 4 W1, 5 ~{RST} (in), 6 CLK (in), 7 GND (power), 8 DQ (in), 9 COUT (out), 10 L0, 11 H0, 12 W0, 13 SOUT (out), 14 VCC (power)

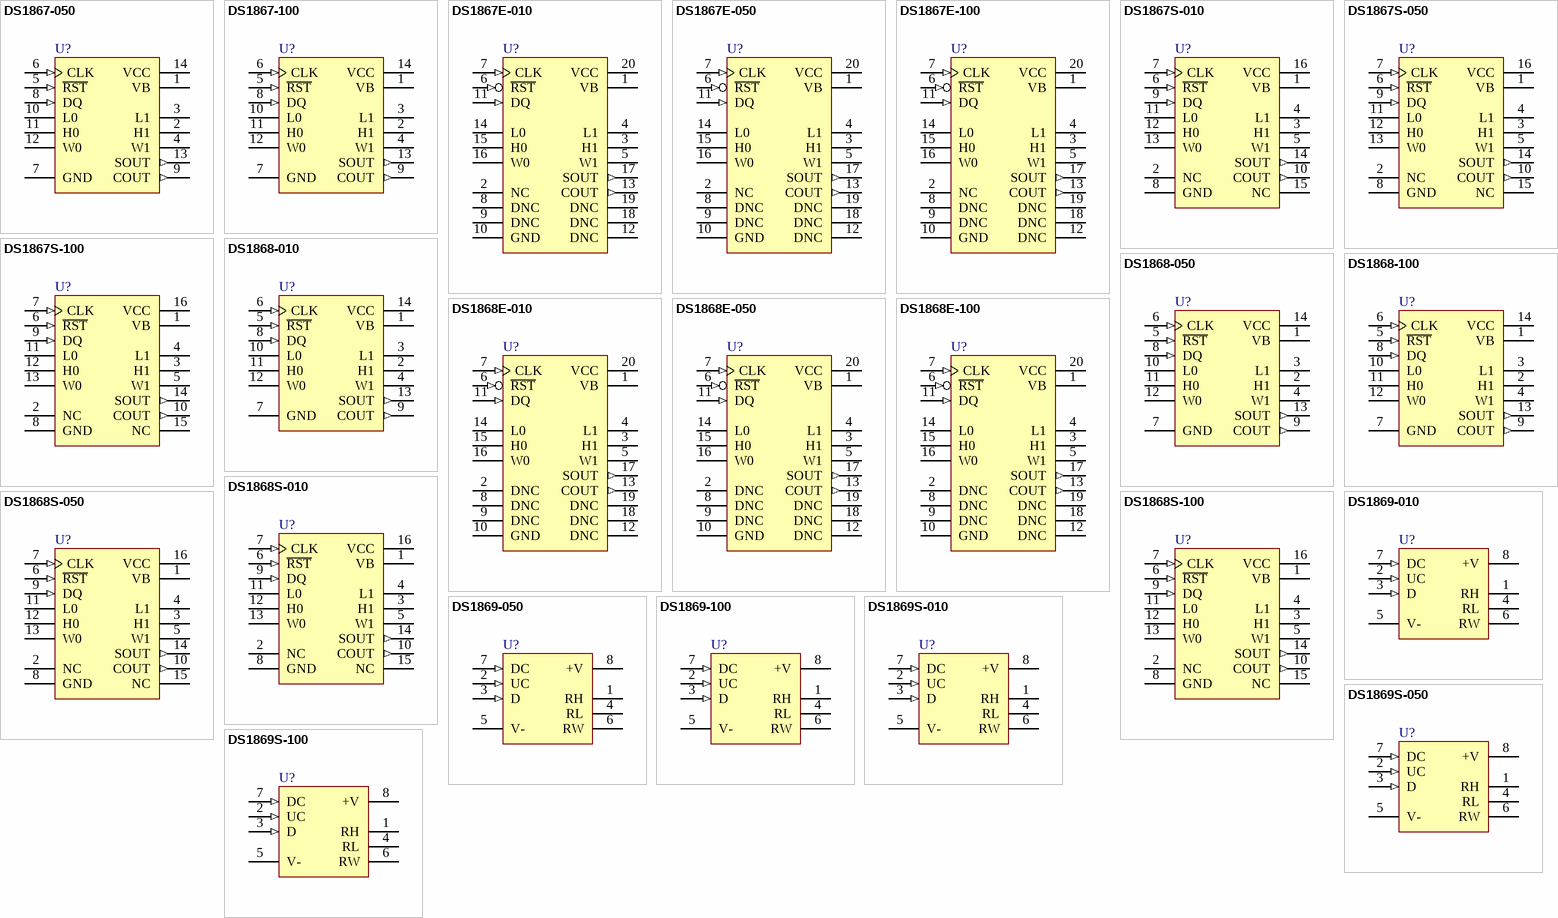
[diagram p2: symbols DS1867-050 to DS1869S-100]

## DS1867-050
designator U?
Dual Digital Potentiometer with EEPROM
footprint DIP14 (DIP, 14-Leads, Row Spacing 7.62mm, Pitch 2.54mm, Body 19.31x6.35mm)
pins: 1 VB (power), 2 H1, 3 L1, 4 W1, 5 ~{RST} (in), 6 CLK (in), 7 GND (power), 8 DQ (in), 9 COUT (out), 10 L0, 11 H0, 12 W0, 13 SOUT (out), 14 VCC (power)

## DS1867-100
designator U?
Dual Digital Potentiometer with EEPROM
footprint DIP14 (DIP, 14-Leads, Row Spacing 7.62mm, Pitch 2.54mm, Body 19.31x6.35mm)
pins: 1 VB (power), 2 H1, 3 L1, 4 W1, 5 ~{RST} (in), 6 CLK (in), 7 GND (power), 8 DQ (in), 9 COUT (out), 10 L0, 11 H0, 12 W0, 13 SOUT (out), 14 VCC (power)

## DS1867E-010
designator U?
Dual Digital Potentiometer with EEPROM; Note: Pin number 2 is Not Connected (NC) Do Not Connect (DNC) pins 8, 9, 12, 18 and 19.
footprint TSSOP20_N (TSOP, 20-Leads, Body 6.5x4.4mm, Pitch 0.65mm, IPC Medium Density)
footprint TSSOP20_L (TSOP, 20-Leads, Body 6.5x4.4mm, Pitch 0.65mm, IPC High Density)
footprint TSSOP20_M (TSOP, 20-Leads, Body 6.5x4.4mm, Pitch 0.65mm, IPC Low Density)
pins: 1 VB (power), 2 NC, 3 H1, 4 L1, 5 W1, 6 ~{RST} (in), 7 CLK (in), 8 DNC, 9 DNC, 10 GND (power), 11 DQ (in), 12 DNC, 13 COUT (out), 14 L0, 15 H0, 16 W0, 17 SOUT (out), 18 DNC, 19 DNC, 20 VCC (power)

## DS1867E-050
designator U?
Dual Digital Potentiometer with EEPROM; Note: Pin number 2 is Not Connected (NC) Do Not Connect (DNC) pins 8, 9, 12, 18 and 19.
footprint TSSOP20_N (TSOP, 20-Leads, Body 6.5x4.4mm, Pitch 0.65mm, IPC Medium Density)
footprint TSSOP20_L (TSOP, 20-Leads, Body 6.5x4.4mm, Pitch 0.65mm, IPC High Density)
footprint TSSOP20_M (TSOP, 20-Leads, Body 6.5x4.4mm, Pitch 0.65mm, IPC Low Density)
pins: 1 VB (power), 2 NC, 3 H1, 4 L1, 5 W1, 6 ~{RST} (in), 7 CLK (in), 8 DNC, 9 DNC, 10 GND (power), 11 DQ (in), 12 DNC, 13 COUT (out), 14 L0, 15 H0, 16 W0, 17 SOUT (out), 18 DNC, 19 DNC, 20 VCC (power)

## DS1867E-100
designator U?
Dual Digital Potentiometer with EEPROM; Note: Pin number 2 is Not Connected (NC) Do Not Connect (DNC) pins 8, 9, 12, 18 and 19.
footprint TSSOP20_N (TSOP, 20-Leads, Body 6.5x4.4mm, Pitch 0.65mm, IPC Medium Density)
footprint TSSOP20_L (TSOP, 20-Leads, Body 6.5x4.4mm, Pitch 0.65mm, IPC High Density)
footprint TSSOP20_M (TSOP, 20-Leads, Body 6.5x4.4mm, Pitch 0.65mm, IPC Low Density)
pins: 1 VB (power), 2 NC, 3 H1, 4 L1, 5 W1, 6 ~{RST} (in), 7 CLK (in), 8 DNC, 9 DNC, 10 GND (power), 11 DQ (in), 12 DNC, 13 COUT (out), 14 L0, 15 H0, 16 W0, 17 SOUT (out), 18 DNC, 19 DNC, 20 VCC (power)

## DS1867S-010
designator U?
Dual Digital Potentiometer with EEPROM; Note: Pin numbers 2 and 15 are Not (internally) Connected (NC)
footprint SOIC16W_N (SOIC, 16-Leads, Body 10.3x7.5mm, Pitch 1.27mm, IPC Medium Density)
footprint SOIC16W_L (SOIC, 16-Leads, Body 10.3x7.5mm, Pitch 1.27mm, IPC High Density)
footprint SOIC16W_M (SOIC, 16-Leads, Body 10.3x7.5mm, Pitch 1.27mm, IPC Low Density)
pins: 1 VB (power), 2 NC, 3 H1, 4 L1, 5 W1, 6 ~{RST} (in), 7 CLK (in), 8 GND (power), 9 DQ (in), 10 COUT (out), 11 L0, 12 H0, 13 W0, 14 SOUT (out), 15 NC, 16 VCC (power)

## DS1867S-050
designator U?
Dual Digital Potentiometer with EEPROM; Note: Pin numbers 2 and 15 are Not (internally) Connected (NC)
footprint SOIC16W_N (SOIC, 16-Leads, Body 10.3x7.5mm, Pitch 1.27mm, IPC Medium Density)
footprint SOIC16W_L (SOIC, 16-Leads, Body 10.3x7.5mm, Pitch 1.27mm, IPC High Density)
footprint SOIC16W_M (SOIC, 16-Leads, Body 10.3x7.5mm, Pitch 1.27mm, IPC Low Density)
pins: 1 VB (power), 2 NC, 3 H1, 4 L1, 5 W1, 6 ~{RST} (in), 7 CLK (in), 8 GND (power), 9 DQ (in), 10 COUT (out), 11 L0, 12 H0, 13 W0, 14 SOUT (out), 15 NC, 16 VCC (power)

## DS1867S-100
designator U?
Dual Digital Potentiometer with EEPROM; Note: Pin numbers 2 and 15 are Not (internally) Connected (NC)
footprint SOIC16W_N (SOIC, 16-Leads, Body 10.3x7.5mm, Pitch 1.27mm, IPC Medium Density)
footprint SOIC16W_L (SOIC, 16-Leads, Body 10.3x7.5mm, Pitch 1.27mm, IPC High Density)
footprint SOIC16W_M (SOIC, 16-Leads, Body 10.3x7.5mm, Pitch 1.27mm, IPC Low Density)
pins: 1 VB (power), 2 NC, 3 H1, 4 L1, 5 W1, 6 ~{RST} (in), 7 CLK (in), 8 GND (power), 9 DQ (in), 10 COUT (out), 11 L0, 12 H0, 13 W0, 14 SOUT (out), 15 NC, 16 VCC (power)

## DS1868-010
designator U?
Dual Digital Potentiometer Chip
footprint DIP14 (DIP, 14-Leads, Row Spacing 7.62mm, Pitch 2.54mm, Body 19.31x6.35mm)
pins: 1 VB (power), 2 H1, 3 L1, 4 W1, 5 ~{RST} (in), 6 CLK (in), 7 GND (power), 8 DQ (in), 9 COUT (out), 10 L0, 11 H0, 12 W0, 13 SOUT (out), 14 VCC (power)

## DS1868-050
designator U?
Dual Digital Potentiometer Chip
footprint DIP14 (DIP, 14-Leads, Row Spacing 7.62mm, Pitch 2.54mm, Body 19.31x6.35mm)
pins: 1 VB (power), 2 H1, 3 L1, 4 W1, 5 ~{RST} (in), 6 CLK (in), 7 GND (power), 8 DQ (in), 9 COUT (out), 10 L0, 11 H0, 12 W0, 13 SOUT (out), 14 VCC (power)

## DS1868-100
designator U?
Dual Digital Potentiometer Chip
footprint DIP14 (DIP, 14-Leads, Row Spacing 7.62mm, Pitch 2.54mm, Body 19.31x6.35mm)
pins: 1 VB (power), 2 H1, 3 L1, 4 W1, 5 ~{RST} (in), 6 CLK (in), 7 GND (power), 8 DQ (in), 9 COUT (out), 10 L0, 11 H0, 12 W0, 13 SOUT (out), 14 VCC (power)

## DS1868E-010
designator U?
Dual Digital Potentiometer Chip; Note: Do Not Connect (DNC) pins 2, 8, 9, 12, 18 and 19.
footprint TSSOP20_N (TSOP, 20-Leads, Body 6.5x4.4mm, Pitch 0.65mm, IPC Medium Density)
footprint TSSOP20_L (TSOP, 20-Leads, Body 6.5x4.4mm, Pitch 0.65mm, IPC High Density)
footprint TSSOP20_M (TSOP, 20-Leads, Body 6.5x4.4mm, Pitch 0.65mm, IPC Low Density)
pins: 1 VB (power), 2 DNC, 3 H1, 4 L1, 5 W1, 6 ~{RST} (in), 7 CLK (in), 8 DNC, 9 DNC, 10 GND (power), 11 DQ (in), 12 DNC, 13 COUT (out), 14 L0, 15 H0, 16 W0, 17 SOUT (out), 18 DNC, 19 DNC, 20 VCC (power)

## DS1868E-050
designator U?
Dual Digital Potentiometer Chip; Note: Do Not Connect (DNC) pins 2, 8, 9, 12, 18 and 19.
footprint TSSOP20_N (TSOP, 20-Leads, Body 6.5x4.4mm, Pitch 0.65mm, IPC Medium Density)
footprint TSSOP20_L (TSOP, 20-Leads, Body 6.5x4.4mm, Pitch 0.65mm, IPC High Density)
footprint TSSOP20_M (TSOP, 20-Leads, Body 6.5x4.4mm, Pitch 0.65mm, IPC Low Density)
pins: 1 VB (power), 2 DNC, 3 H1, 4 L1, 5 W1, 6 ~{RST} (in), 7 CLK (in), 8 DNC, 9 DNC, 10 GND (power), 11 DQ (in), 12 DNC, 13 COUT (out), 14 L0, 15 H0, 16 W0, 17 SOUT (out), 18 DNC, 19 DNC, 20 VCC (power)

## DS1868E-100
designator U?
Dual Digital Potentiometer Chip; Note: Do Not Connect (DNC) pins 2, 8, 9, 12, 18 and 19.
footprint TSSOP20_N (TSOP, 20-Leads, Body 6.5x4.4mm, Pitch 0.65mm, IPC Medium Density)
footprint TSSOP20_L (TSOP, 20-Leads, Body 6.5x4.4mm, Pitch 0.65mm, IPC High Density)
footprint TSSOP20_M (TSOP, 20-Leads, Body 6.5x4.4mm, Pitch 0.65mm, IPC Low Density)
pins: 1 VB (power), 2 DNC, 3 H1, 4 L1, 5 W1, 6 ~{RST} (in), 7 CLK (in), 8 DNC, 9 DNC, 10 GND (power), 11 DQ (in), 12 DNC, 13 COUT (out), 14 L0, 15 H0, 16 W0, 17 SOUT (out), 18 DNC, 19 DNC, 20 VCC (power)

## DS1868S-010
designator U?
Dual Digital Potentiometer Chip; Note: Pin numbers 2 and 15 are Not (internally) Connected (NC)
footprint SOIC16W_N (SOIC, 16-Leads, Body 10.3x7.5mm, Pitch 1.27mm, IPC Medium Density)
footprint SOIC16W_L (SOIC, 16-Leads, Body 10.3x7.5mm, Pitch 1.27mm, IPC High Density)
footprint SOIC16W_M (SOIC, 16-Leads, Body 10.3x7.5mm, Pitch 1.27mm, IPC Low Density)
pins: 1 VB (power), 2 NC, 3 H1, 4 L1, 5 W1, 6 ~{RST} (in), 7 CLK (in), 8 GND (power), 9 DQ (in), 10 COUT (out), 11 L0, 12 H0, 13 W0, 14 SOUT (out), 15 NC, 16 VCC (power)

## DS1868S-050
designator U?
Dual Digital Potentiometer Chip; Note: Pin numbers 2 and 15 are Not (internally) Connected (NC)
footprint SOIC16W_N (SOIC, 16-Leads, Body 10.3x7.5mm, Pitch 1.27mm, IPC Medium Density)
footprint SOIC16W_L (SOIC, 16-Leads, Body 10.3x7.5mm, Pitch 1.27mm, IPC High Density)
footprint SOIC16W_M (SOIC, 16-Leads, Body 10.3x7.5mm, Pitch 1.27mm, IPC Low Density)
pins: 1 VB (power), 2 NC, 3 H1, 4 L1, 5 W1, 6 ~{RST} (in), 7 CLK (in), 8 GND (power), 9 DQ (in), 10 COUT (out), 11 L0, 12 H0, 13 W0, 14 SOUT (out), 15 NC, 16 VCC (power)

## DS1868S-100
designator U?
Dual Digital Potentiometer Chip; Note: Pin numbers 2 and 15 are Not (internally) Connected (NC)
footprint SOIC16W_N (SOIC, 16-Leads, Body 10.3x7.5mm, Pitch 1.27mm, IPC Medium Density)
footprint SOIC16W_L (SOIC, 16-Leads, Body 10.3x7.5mm, Pitch 1.27mm, IPC High Density)
footprint SOIC16W_M (SOIC, 16-Leads, Body 10.3x7.5mm, Pitch 1.27mm, IPC Low Density)
pins: 1 VB (power), 2 NC, 3 H1, 4 L1, 5 W1, 6 ~{RST} (in), 7 CLK (in), 8 GND (power), 9 DQ (in), 10 COUT (out), 11 L0, 12 H0, 13 W0, 14 SOUT (out), 15 NC, 16 VCC (power)

## DS1869-010
designator U?
3V Dallastat Electronic Digital Rheostat
footprint DIP8 (DIP, 8-Leads, Row Spacing 7.62mm, Pitch 2.54mm, Body 9.65x6.35mm)
pins: 1 RH, 2 UC (in), 3 D (in), 4 RL, 5 V- (power), 6 RW, 7 DC (in), 8 +V (power)

## DS1869-050
designator U?
3V Dallastat Electronic Digital Rheostat
footprint DIP8 (DIP, 8-Leads, Row Spacing 7.62mm, Pitch 2.54mm, Body 9.65x6.35mm)
pins: 1 RH, 2 UC (in), 3 D (in), 4 RL, 5 V- (power), 6 RW, 7 DC (in), 8 +V (power)

## DS1869-100
designator U?
3V Dallastat Electronic Digital Rheostat
footprint DIP8 (DIP, 8-Leads, Row Spacing 7.62mm, Pitch 2.54mm, Body 9.65x6.35mm)
pins: 1 RH, 2 UC (in), 3 D (in), 4 RL, 5 V- (power), 6 RW, 7 DC (in), 8 +V (power)

## DS1869S-010
designator U?
3V Dallastat Electronic Digital Rheostat
footprint SOIC8W_N (SOP, 8-Leads, Body 5.3x5.3mm, Pitch 1.27mm, IPC Medium Density)
footprint SOIC8W_L (SOP, 8-Leads, Body 5.3x5.3mm, Pitch 1.27mm, IPC High Density)
footprint SOIC8W_M (SOP, 8-Leads, Body 5.3x5.3mm, Pitch 1.27mm, IPC Low Density)
pins: 1 RH, 2 UC (in), 3 D (in), 4 RL, 5 V- (power), 6 RW, 7 DC (in), 8 +V (power)

## DS1869S-050
designator U?
3V Dallastat Electronic Digital Rheostat
footprint SOIC8W_N (SOP, 8-Leads, Body 5.3x5.3mm, Pitch 1.27mm, IPC Medium Density)
footprint SOIC8W_L (SOP, 8-Leads, Body 5.3x5.3mm, Pitch 1.27mm, IPC High Density)
footprint SOIC8W_M (SOP, 8-Leads, Body 5.3x5.3mm, Pitch 1.27mm, IPC Low Density)
pins: 1 RH, 2 UC (in), 3 D (in), 4 RL, 5 V- (power), 6 RW, 7 DC (in), 8 +V (power)

## DS1869S-100
designator U?
3V Dallastat Electronic Digital Rheostat
footprint SOIC8W_N (SOP, 8-Leads, Body 5.3x5.3mm, Pitch 1.27mm, IPC Medium Density)
footprint SOIC8W_L (SOP, 8-Leads, Body 5.3x5.3mm, Pitch 1.27mm, IPC High Density)
footprint SOIC8W_M (SOP, 8-Leads, Body 5.3x5.3mm, Pitch 1.27mm, IPC Low Density)
pins: 1 RH, 2 UC (in), 3 D (in), 4 RL, 5 V- (power), 6 RW, 7 DC (in), 8 +V (power)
